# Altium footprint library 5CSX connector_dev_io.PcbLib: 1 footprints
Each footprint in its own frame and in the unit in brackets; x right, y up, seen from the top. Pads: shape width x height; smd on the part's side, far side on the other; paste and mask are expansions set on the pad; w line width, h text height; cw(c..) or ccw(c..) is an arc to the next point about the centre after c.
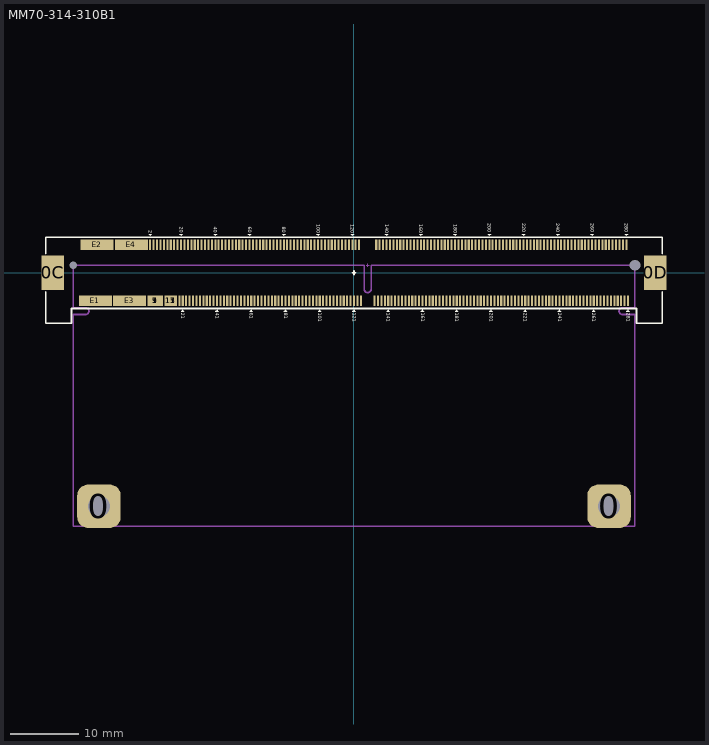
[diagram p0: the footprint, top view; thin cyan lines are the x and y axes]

## MM70-314-310B1 [mm]
pads (284):
  rrect50% 6.35x6.35 hole 3.175: 0(-37.236,-34.087) 0(37.236,-34.087)
  round 0 hole 1.1 unplated: 0A(-41,1.1)
  round 0 hole 1.6 unplated: 0B(41,1.1)
  rect 3.3x5 smd: 0C(-43.95,0) 0D(43.95,0)
  rect 2.3x1.5 smd paste-0.225: 1(-29,-4.1) 3(-29,-4.1) 5(-29,-4.1) 7(-29,-4.1) 9(-29,-4.1)
  rect 0.3x1.5 smd paste+0: 2(-29.75,4.1) 4(-29.25,4.1) 6(-28.75,4.1) 8(-28.25,4.1) 10(-27.75,4.1) 12(-27.25,4.1) 14(-26.75,4.1) 16(-26.25,4.1) 18(-25.75,4.1) 19(-25.5,-4.1) 20(-25.25,4.1) 21(-25,-4.1) 22(-24.75,4.1) 23(-24.5,-4.1) 24(-24.25,4.1) 25(-24,-4.1) 26(-23.75,4.1) 27(-23.5,-4.1) 28(-23.25,4.1) 29(-23,-4.1) 30(-22.75,4.1) 31(-22.5,-4.1) 32(-22.25,4.1) 33(-22,-4.1) 34(-21.75,4.1) 35(-21.5,-4.1) 36(-21.25,4.1) 37(-21,-4.1) 38(-20.75,4.1) 39(-20.5,-4.1) 40(-20.25,4.1) 41(-20,-4.1) 42(-19.75,4.1) 43(-19.5,-4.1) 44(-19.25,4.1) 45(-19,-4.1) 46(-18.75,4.1) 47(-18.5,-4.1) 48(-18.25,4.1) 49(-18,-4.1) 50(-17.75,4.1) 51(-17.5,-4.1) 52(-17.25,4.1) 53(-17,-4.1) 54(-16.75,4.1) 55(-16.5,-4.1) 56(-16.25,4.1) 57(-16,-4.1) 58(-15.75,4.1) 59(-15.5,-4.1) 60(-15.25,4.1) 61(-15,-4.1) 62(-14.75,4.1) 63(-14.5,-4.1) 64(-14.25,4.1) 65(-14,-4.1) 66(-13.75,4.1) 67(-13.5,-4.1) 68(-13.25,4.1) 69(-13,-4.1) 70(-12.75,4.1) 71(-12.5,-4.1) 72(-12.25,4.1) 73(-12,-4.1) 74(-11.75,4.1) 75(-11.5,-4.1) 76(-11.25,4.1) 77(-11,-4.1) 78(-10.75,4.1) 79(-10.5,-4.1) 80(-10.25,4.1) 81(-10,-4.1) 82(-9.75,4.1) 83(-9.5,-4.1) 84(-9.25,4.1) 85(-9,-4.1) 86(-8.75,4.1) 87(-8.5,-4.1) 88(-8.25,4.1) 89(-8,-4.1) 90(-7.75,4.1) 91(-7.5,-4.1) 92(-7.25,4.1) 93(-7,-4.1) 94(-6.75,4.1) 95(-6.5,-4.1) 96(-6.25,4.1) 97(-6,-4.1) 98(-5.75,4.1) 99(-5.5,-4.1) 100(-5.25,4.1) 101(-5,-4.1) 102(-4.75,4.1) 103(-4.5,-4.1) 104(-4.25,4.1) 105(-4,-4.1) 106(-3.75,4.1) 107(-3.5,-4.1) 108(-3.25,4.1) 109(-3,-4.1) 110(-2.75,4.1) 111(-2.5,-4.1) 112(-2.25,4.1) 113(-2,-4.1) 114(-1.75,4.1) 115(-1.5,-4.1) 116(-1.25,4.1) 117(-1,-4.1) 118(-0.75,4.1) 119(-0.5,-4.1) 120(-0.25,4.1) 121(0,-4.1) 122(0.25,4.1) 123(0.5,-4.1) 124(0.75,4.1) 125(1,-4.1) 133(3,-4.1) 134(3.25,4.1) 135(3.5,-4.1) 136(3.75,4.1) 137(4,-4.1) 138(4.25,4.1) 139(4.5,-4.1) 140(4.75,4.1) 141(5,-4.1) 142(5.25,4.1) 143(5.5,-4.1) 144(5.75,4.1) 145(6,-4.1) 146(6.25,4.1) 147(6.5,-4.1) 148(6.75,4.1) 149(7,-4.1) 150(7.25,4.1) 151(7.5,-4.1) 152(7.75,4.1) 153(8,-4.1) 154(8.25,4.1) 155(8.5,-4.1) 156(8.75,4.1) 157(9,-4.1) 158(9.25,4.1) 159(9.5,-4.1) 160(9.75,4.1) 161(10,-4.1) 162(10.25,4.1) 163(10.5,-4.1) 164(10.75,4.1) 165(11,-4.1) 166(11.25,4.1) 167(11.5,-4.1) 168(11.75,4.1) 169(12,-4.1) 170(12.25,4.1) 171(12.5,-4.1) 172(12.75,4.1) 173(13,-4.1) 174(13.25,4.1) 175(13.5,-4.1) 176(13.75,4.1) 177(14,-4.1) 178(14.25,4.1) 179(14.5,-4.1) 180(14.75,4.1) 181(15,-4.1) 182(15.25,4.1) 183(15.5,-4.1) 184(15.75,4.1) 185(16,-4.1) 186(16.25,4.1) 187(16.5,-4.1) 188(16.75,4.1) 189(17,-4.1) 190(17.25,4.1) 191(17.5,-4.1) 192(17.75,4.1) 193(18,-4.1) 194(18.25,4.1) 195(18.5,-4.1) 196(18.75,4.1) 197(19,-4.1) 198(19.25,4.1) 199(19.5,-4.1) 200(19.75,4.1) 201(20,-4.1) 202(20.25,4.1) 203(20.5,-4.1) 204(20.75,4.1) 205(21,-4.1) 206(21.25,4.1) 207(21.5,-4.1) 208(21.75,4.1) 209(22,-4.1) 210(22.25,4.1) 211(22.5,-4.1) 212(22.75,4.1) 213(23,-4.1) 214(23.25,4.1) 215(23.5,-4.1) 216(23.75,4.1) 217(24,-4.1) 218(24.25,4.1) 219(24.5,-4.1) 220(24.75,4.1) 221(25,-4.1) 222(25.25,4.1) 223(25.5,-4.1) 224(25.75,4.1) 225(26,-4.1) 226(26.25,4.1) 227(26.5,-4.1) 228(26.75,4.1) 229(27,-4.1) 230(27.25,4.1) 231(27.5,-4.1) 232(27.75,4.1) 233(28,-4.1) 234(28.25,4.1) 235(28.5,-4.1) 236(28.75,4.1) 237(29,-4.1) 238(29.25,4.1) 239(29.5,-4.1) 240(29.75,4.1) 241(30,-4.1) 242(30.25,4.1) 243(30.5,-4.1) 244(30.75,4.1) 245(31,-4.1) 246(31.25,4.1) 247(31.5,-4.1) 248(31.75,4.1) 249(32,-4.1) 250(32.25,4.1) 251(32.5,-4.1) 252(32.75,4.1) 253(33,-4.1) 254(33.25,4.1) 255(33.5,-4.1) 256(33.75,4.1) 257(34,-4.1) 258(34.25,4.1) 259(34.5,-4.1) 260(34.75,4.1) 261(35,-4.1) 262(35.25,4.1) 263(35.5,-4.1) 264(35.75,4.1) 265(36,-4.1) 266(36.25,4.1) 267(36.5,-4.1) 268(36.75,4.1) 269(37,-4.1) 270(37.25,4.1) 271(37.5,-4.1) 272(37.75,4.1) 273(38,-4.1) 274(38.25,4.1) 275(38.5,-4.1) 276(38.75,4.1) 277(39,-4.1) 278(39.25,4.1) 279(39.5,-4.1) 280(39.75,4.1) 281(40,-4.1)
  rect 1.8x1.5 smd paste-0.225: 11(-26.75,-4.1) 13(-26.75,-4.1) 15(-26.75,-4.1) 17(-26.75,-4.1)
  rect 4.8x1.5 smd paste-0.225: E1(-37.75,-4.1) E2(-37.5,4.1) E3(-32.75,-4.1) E4(-32.5,4.1)
Top Overlay:
  drawing of 41 lines, arcs and shapes, not listed
  text "261" at 34.787,-5.806 h0.51
  text "241" at 29.787,-5.806 h0.51
  text "221" at 24.787,-5.806 h0.51
  text "201" at 19.787,-5.806 h0.51
  text "181" at 14.787,-5.806 h0.51
  text "161" at 9.787,-5.806 h0.51
  text "141" at 4.787,-5.806 h0.51
  text "121" at -0.213,-5.806 h0.51
  text "101" at -5.213,-5.806 h0.51
  text "81" at -10.213,-5.806 h0.51
  text "61" at -15.213,-5.806 h0.51
  text "41" at -20.213,-5.806 h0.51
  text "21" at -25.213,-5.806 h0.51
  text "2" at -29.965,6.184 h0.51
  text "280" at 39.535,7.2 h0.51
  text "260" at 34.535,7.2 h0.51
  text "240" at 29.535,7.2 h0.51
  text "220" at 24.535,7.2 h0.51
  text "200" at 19.535,7.2 h0.51
  text "180" at 14.535,7.115 h0.51
  text "160" at 9.535,7.115 h0.51
  text "140" at 4.535,7.115 h0.51
  text "120" at -0.465,7.115 h0.51
  text "100" at -5.465,7.115 h0.51
  text "80" at -10.465,6.692 h0.51
  text "60" at -15.465,6.692 h0.51
  text "40" at -20.465,6.692 h0.51
  text "20" at -25.465,6.692 h0.51
  text "281" at 39.788,-5.806 h0.51
Mechanical 16:
  lines w0.051: 1.8,1.1 2.2,1.1 ; 2,0.9 2,1.3
  lines w0.254: -41,-37 -41,-6.1 -39.2,-6.1 ccw(c-39.2,-5.6) -39.2,-5.1 -41,-5.1 -41,1.1 1.5,1.1 1.5,-2.4 ccw(c2,-2.4) 2.5,-2.4 2.5,1.1 41,1.1 41,-5.1 39.2,-5.1 ccw(c39.2,-5.6) 39.2,-6.1 41,-6.1 41,-37 -41,-37
3D body: height 6.69, standoff -1.01, extent -44.949,-7.358 44.951,4.842
3D body: height 7.32, standoff 1.79, extent -41.004,-37.897 40.996,1.103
